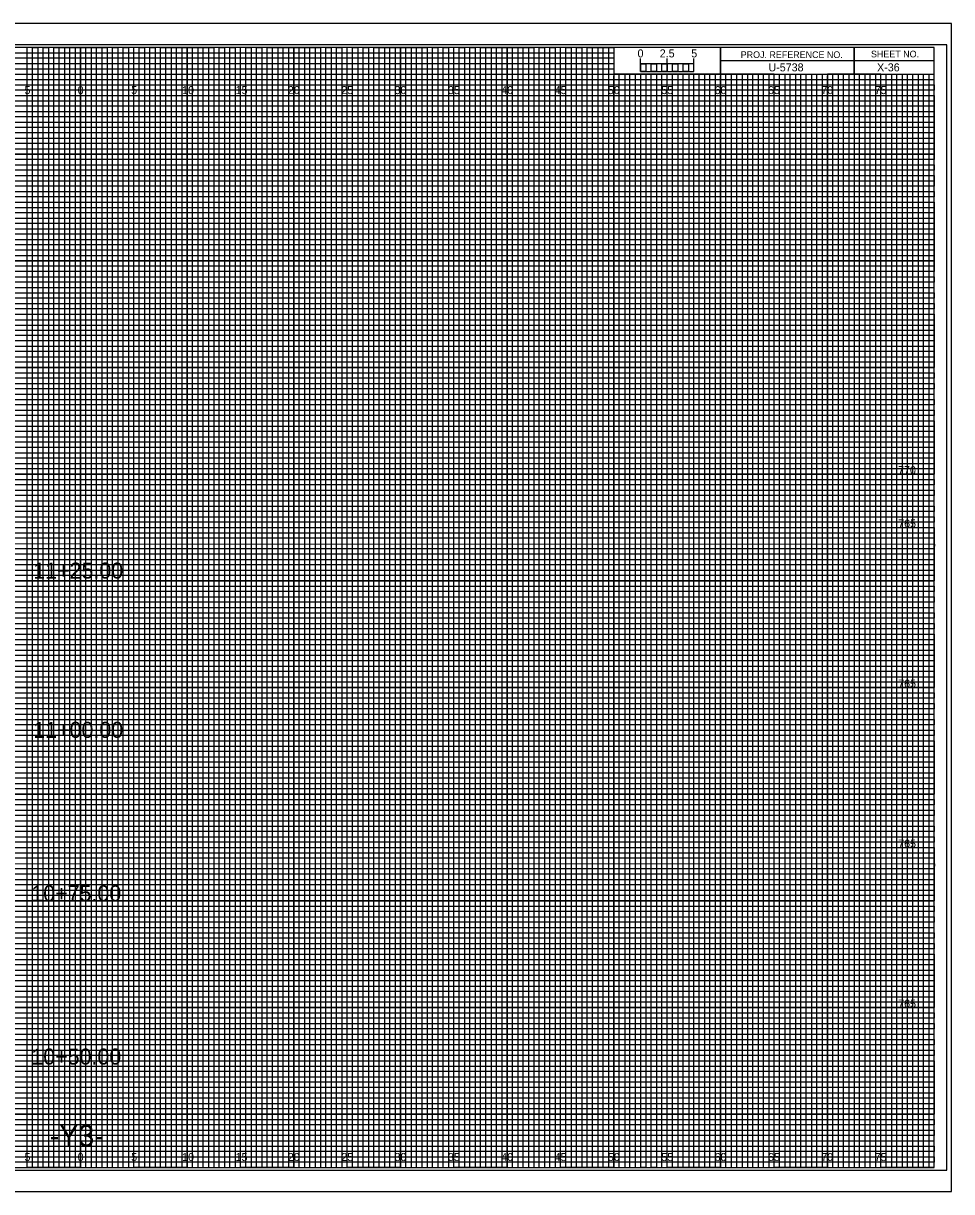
# Model space of a CAD drawing. Extents: x -7 to 162, y -2 to 107.
# Drawn here: x 74.6 to 161.7, y -2.3 to 107.3 of the extents above; entities that cross this region are included whole.
import ezdxf

# ---------------------------------------------------------------- set-up
doc = ezdxf.new("R2010")
doc.units = 0
for name, color, linetype in [('Exist XS Center Line Elevation Label', 7, 'Continuous'), ('Prop CMT Pvmt Course 1', 7, 'Continuous'), ('Prop CMT Pvmt Course 2', 7, 'Continuous'), ('Prop CMT Pvmt Course 3', 7, 'Continuous'), ('Prop CMT Pvmt Surface', 7, 'Continuous'), ('Prop CMT Pvmt Surface Shoulder', 7, 'Continuous'), ('Prop CMT Shld Paved Course 1', 7, 'Continuous'), ('Prop CMT Shld Paved Course 2', 7, 'Continuous'), ('Prop CMT Shld Paved Course 3', 7, 'Continuous'), ('Prop CMT Subgrade Earthwork', 7, 'Continuous'), ('Prop XS Alignment Label', 7, 'Continuous'), ('Prop XS Bar Scale Labels', 7, 'Continuous'), ('Prop XS Project Number', 7, 'Continuous'), ('Prop XS SE Text', 7, 'Continuous'), ('Prop XS Sheet Number', 7, 'Continuous'), ('Prop XS Station Labels', 7, 'Continuous'), ('Scratch_Level_5', 7, 'Continuous')]:
    doc.layers.add(name, color=color, linetype=linetype)

msp = doc.modelspace()

# ---------------------------------------------------------------- linework, layer by layer
at = {"layer": 'Prop CMT Pvmt Course 1'}
msp.add_lwpolyline([(-6.7, -2.25), (161.65, -2.25), (161.65, 107.25), (-6.7, 107.25)], close=True, dxfattribs=at)
at = {"layer": 'Prop CMT Pvmt Course 2'}
msp.add_lwpolyline([(-5.4, -0.25), (161.2, -0.25), (161.2, 105.25), (-5.4, 105.25)], close=True, dxfattribs=at)
at = {"layer": 'Prop CMT Pvmt Course 3'}
for p, q in [((75, 0), (75, 105)), ((80, 0), (80, 105)), ((85, 0), (85, 105)), ((90, 0), (90, 105)), ((95, 0), (95, 105)), ((100, 0), (100, 105)), ((105, 0), (105, 105)), ((110, 0), (110, 105)), ((115, 0), (115, 105)), ((120, 0), (120, 105)), ((125, 0), (125, 105)), ((130, 0), (130, 102.34)), ((135, 0), (135, 102.34)), ((140, 0), (140, 102.34)), ((145, 0), (145, 102.34)), ((150, 0), (150, 102.34)), ((155, 0), (155, 102.34)), ((0, 100), (160, 100)), ((0, 95), (160, 95)), ((0, 90), (160, 90)), ((0, 85), (160, 85)), ((0, 80), (160, 80)), ((0, 75), (160, 75)), ((0, 70), (160, 70)), ((0, 65), (160, 65)), ((0, 60), (160, 60)), ((0, 55), (160, 55)), ((0, 50), (160, 50)), ((0, 45), (160, 45)), ((0, 40), (160, 40)), ((0, 35), (160, 35)), ((0, 30), (160, 30)), ((0, 25), (160, 25)), ((0, 20), (160, 20)), ((0, 15), (160, 15)), ((0, 10), (160, 10)), ((0, 5), (160, 5))]:
    msp.add_line(p, q, dxfattribs=at)
at = {"layer": 'Prop CMT Pvmt Surface'}
for p, q in [((133.5, 102.5), (133, 102.5)), ((133, 102.5), (133, 0)), ((133.5, 0), (133.5, 102.5)), ((134.5, 102.5), (134, 102.5)), ((134, 102.5), (134, 0)), ((134.5, 0), (134.5, 102.5)), ((133, 0), (132.5, 0)), ((134, 0), (133.5, 0))]:
    msp.add_line(p, q, dxfattribs=at)
for points in [[(75, 0), (75.5, 0), (75.5, 105), (76, 105), (76, 0)], [(76, 0), (76.5, 0), (76.5, 105), (77, 105), (77, 0)], [(77.5, 0), (78, 0), (78, 105), (78.5, 105), (78.5, 0)], [(78.5, 0), (79, 0), (79, 105), (79.5, 105), (79.5, 0)], [(80, 0), (80.5, 0), (80.5, 105), (81, 105), (81, 0)], [(81, 0), (81.5, 0), (81.5, 105), (82, 105), (82, 0)], [(82.5, 0), (83, 0), (83, 105), (83.5, 105), (83.5, 0)], [(83.5, 0), (84, 0), (84, 105), (84.5, 105), (84.5, 0)], [(85, 0), (85.5, 0), (85.5, 105), (86, 105), (86, 0)], [(86, 0), (86.5, 0), (86.5, 105), (87, 105), (87, 0)], [(87.5, 0), (88, 0), (88, 105), (88.5, 105), (88.5, 0)], [(88.5, 0), (89, 0), (89, 105), (89.5, 105), (89.5, 0)], [(90, 0), (90.5, 0), (90.5, 105), (91, 105), (91, 0)], [(91, 0), (91.5, 0), (91.5, 105), (92, 105), (92, 0)], [(92.5, 0), (93, 0), (93, 105), (93.5, 105), (93.5, 0)], [(93.5, 0), (94, 0), (94, 105), (94.5, 105), (94.5, 0)], [(95, 0), (95.5, 0), (95.5, 105), (96, 105), (96, 0)], [(96, 0), (96.5, 0), (96.5, 105), (97, 105), (97, 0)], [(97.5, 0), (98, 0), (98, 105), (98.5, 105), (98.5, 0)], [(98.5, 0), (99, 0), (99, 105), (99.5, 105), (99.5, 0)], [(100, 0), (100.5, 0), (100.5, 105), (101, 105), (101, 0)], [(101, 0), (101.5, 0), (101.5, 105), (102, 105), (102, 0)], [(102.5, 0), (103, 0), (103, 105), (103.5, 105), (103.5, 0)], [(103.5, 0), (104, 0), (104, 105), (104.5, 105), (104.5, 0)], [(105, 0), (105.5, 0), (105.5, 105), (106, 105), (106, 0)], [(106, 0), (106.5, 0), (106.5, 105), (107, 105), (107, 0)], [(107.5, 0), (108, 0), (108, 105), (108.5, 105), (108.5, 0)], [(108.5, 0), (109, 0), (109, 105), (109.5, 105), (109.5, 0)], [(110, 0), (110.5, 0), (110.5, 105), (111, 105), (111, 0)], [(111, 0), (111.5, 0), (111.5, 105), (112, 105), (112, 0)], [(112.5, 0), (113, 0), (113, 105), (113.5, 105), (113.5, 0)], [(113.5, 0), (114, 0), (114, 105), (114.5, 105), (114.5, 0)], [(115, 0), (115.5, 0), (115.5, 105), (116, 105), (116, 0)], [(116, 0), (116.5, 0), (116.5, 105), (117, 105), (117, 0)], [(117.5, 0), (118, 0), (118, 105), (118.5, 105), (118.5, 0)], [(118.5, 0), (119, 0), (119, 105), (119.5, 105), (119.5, 0)], [(120, 0), (120.5, 0), (120.5, 105), (121, 105), (121, 0)], [(121, 0), (121.5, 0), (121.5, 105), (122, 105), (122, 0)], [(122.5, 0), (123, 0), (123, 105), (123.5, 105), (123.5, 0)], [(123.5, 0), (124, 0), (124, 105), (124.5, 105), (124.5, 0)], [(125, 0), (125.5, 0), (125.5, 105), (126, 105), (126, 0)], [(126, 0), (126.5, 0), (126.5, 105), (127, 105), (127, 0)], [(127.5, 0), (128, 0), (128, 105), (128.5, 105), (128.5, 0)], [(128.5, 0), (129, 0), (129, 105), (129.5, 105), (129.5, 0)], [(130, 0), (130.5, 0), (130.5, 102.5), (131.01, 102.5), (131.01, 0)], [(131, 0), (131.5, 0), (131.5, 102.5), (132, 102.5), (132, 0)], [(135, 0), (135.49, 0), (135.49, 102.5), (136, 102.5), (136, 0)], [(136, 0), (136.5, 0), (136.5, 102.5), (137.03, 102.5), (137.03, 0)], [(137.5, 0), (138, 0), (138, 102.5), (138.5, 102.5), (138.5, 0)], [(138.5, 0), (139, 0), (139, 102.5), (139.5, 102.5), (139.5, 0)], [(140, 0), (140.5, 0), (140.5, 102.5), (141, 102.5), (141, 0)], [(141, 0), (141.5, 0), (141.5, 102.5), (142, 102.5), (142, 0)], [(142.5, 0), (143, 0), (143, 102.5), (143.5, 102.5), (143.5, 0)], [(143.5, 0), (144, 0), (144, 102.5), (144.5, 102.5), (144.5, 0)], [(145, 0), (145.5, 0), (145.5, 102.5), (146, 102.5), (146, 0)], [(146, 0), (146.5, 0), (146.5, 102.5), (147, 102.5), (147, 0)], [(147.5, 0), (148, 0), (148, 102.5), (148.5, 102.5), (148.5, 0)], [(148.5, 0), (149, 0), (149, 102.5), (149.5, 102.5), (149.5, 0)], [(150, 0), (150.5, 0), (150.5, 102.5), (151, 102.5), (151, 0)], [(151, 0), (151.5, 0), (151.5, 102.5), (152, 102.5), (152, 0)], [(152.5, 0), (153, 0), (153, 102.5), (153.5, 102.5), (153.5, 0)], [(153.5, 0), (154, 0), (154, 102.5), (154.5, 102.5), (154.5, 0)], [(155, 0), (155.5, 0), (155.5, 102.5), (156, 102.5), (156, 0)], [(156, 0), (156.5, 0), (156.5, 102.5), (157, 102.5), (157, 0)], [(157.5, 0), (158, 0), (158, 102.5), (158.5, 102.5), (158.5, 0)], [(158.5, 0), (159, 0), (159, 102.5), (159.5, 102.5), (159.5, 0)]]:
    msp.add_lwpolyline(points, dxfattribs=at)
at = {"layer": 'Prop CMT Pvmt Surface Shoulder'}
for p, q in [((132.5, 102.75), (132.5, 103.95)), ((132.5, 103.45), (132.5, 103.95)), ((135, 102.75), (135, 103.95)), ((137.5, 102.75), (137.5, 103.95)), ((137.5, 103.45), (137.5, 103.95))]:
    msp.add_line(p, q, dxfattribs=at)
for points in [[(137.5, 103.45), (132.5, 103.45), (132.5, 102.75), (137.5, 102.75)], [(132.5, 103.45), (133, 103.45), (133, 102.75), (132.5, 102.75)], [(133.5, 103.45), (134, 103.45), (134, 102.75), (133.5, 102.75)], [(134.5, 103.45), (135, 103.45), (135, 102.75), (134.5, 102.75)], [(135.5, 103.45), (136, 103.45), (136, 102.75), (135.5, 102.75)], [(136.5, 103.45), (137, 103.45), (137, 102.75), (136.5, 102.75)]]:
    msp.add_lwpolyline(points, close=True, dxfattribs=at)
at = {"layer": 'Prop CMT Shld Paved Course 1'}
for p, q in [((75, 105), (70, 105)), ((75, 0), (75, 105)), ((85, 105), (80, 105)), ((80, 105), (80, 0)), ((85, 0), (85, 105)), ((95, 105), (90, 105)), ((90, 105), (90, 0)), ((95, 0), (95, 105)), ((105, 105), (100, 105)), ((100, 105), (100, 0)), ((105, 0), (105, 105)), ((115, 105), (110, 105)), ((110, 105), (110, 0)), ((115, 0), (115, 105)), ((125, 105), (120, 105)), ((120, 105), (120, 0)), ((125, 0), (125, 105)), ((130, 105), (130, 0)), ((135, 0), (135, 102.5)), ((145, 102.5), (140, 102.5)), ((140, 102.5), (140, 0)), ((145, 0), (145, 102.5)), ((155, 102.5), (150, 102.5)), ((150, 102.5), (150, 0)), ((155, 0), (155, 102.5)), ((80, 0), (75, 0)), ((90, 0), (85, 0)), ((100, 0), (95, 0)), ((110, 0), (105, 0)), ((120, 0), (115, 0)), ((130, 0), (125, 0)), ((140, 0), (135, 0)), ((150, 0), (145, 0)), ((160, 0), (155, 0)), ((160, 0), (160, 0))]:
    msp.add_line(p, q, dxfattribs=at)
for points in [[(0, 100), (160, 100), (160, 95), (0, 95)], [(0, 90), (160, 90), (160, 85), (0, 85)], [(0, 80), (160, 80), (160, 75), (0, 75)], [(0, 70), (160, 70), (160, 65), (0, 65)], [(0, 60), (160, 60), (160, 55), (0, 55)], [(0, 50), (160, 50), (160, 45), (0, 45)], [(0, 40), (160, 40), (160, 35), (0, 35)], [(0, 30), (160, 30), (160, 25), (0, 25)], [(0, 20), (160, 20), (160, 15), (0, 15)], [(0, 10), (160, 10), (160, 5), (0, 5)]]:
    msp.add_lwpolyline(points, dxfattribs=at)
at = {"layer": 'Prop CMT Shld Paved Course 2'}
for points in [[(72.5, 0), (77.5, 0), (77.5, 105), (82.5, 105), (82.5, 0), (87.5, 0), (87.5, 105), (92.5, 105), (92.5, 0), (97.5, 0), (97.5, 105), (102.5, 105), (102.5, 0), (107.5, 0), (107.5, 105), (112.5, 105), (112.5, 0), (117.5, 0), (117.5, 105), (122.5, 105), (122.5, 0), (127.5, 0), (127.5, 105), (129.97, 105), (130, 105), (130, 102.5), (132.5, 102.5), (132.5, 0), (137.5, 0), (137.5, 102.5), (142.5, 102.5), (142.5, 0), (147.5, 0), (147.5, 102.5), (152.5, 102.5), (152.5, 0), (157.5, 0), (157.5, 102.5)], [(0, 102.5), (137.5, 102.5)], [(0, 92.5), (160, 92.5), (160, 97.5), (0, 97.5)], [(0, 82.5), (160, 82.5), (160, 87.5), (0, 87.5)], [(0, 72.5), (160, 72.5), (160, 77.5), (0, 77.5)], [(0, 62.5), (160, 62.5), (160, 67.5), (0, 67.5)], [(0, 52.5), (160, 52.5), (160, 57.5), (0, 57.5)], [(0, 42.5), (160, 42.5), (160, 47.5), (0, 47.5)], [(0, 32.5), (160, 32.5), (160, 37.5), (0, 37.5)], [(0, 22.5), (160, 22.5), (160, 27.5), (0, 27.5)], [(0, 12.5), (160, 12.5), (160, 17.5), (0, 17.5)], [(0, 2.5), (160, 2.5), (160, 7.5), (0, 7.5)]]:
    msp.add_lwpolyline(points, dxfattribs=at)
at = {"layer": 'Prop CMT Shld Paved Course 3'}
for p, q in [((0, 104.5), (130, 104.5)), ((130, 104.5), (130, 103.99)), ((130, 103.99), (0, 103.99)), ((0, 103.5), (130, 103.5)), ((130, 102.95), (0, 102.95)), ((130, 103.5), (130, 102.95)), ((0, 102), (160, 102))]:
    msp.add_line(p, q, dxfattribs=at)
for points in [[(0, 101.5), (135, 101.5), (160, 101.5), (160, 101), (0, 101)], [(0, 100.5), (160, 100.5), (160, 99.5), (0, 99.5)], [(0, 99), (160, 99), (160, 98.5), (0, 98.49)], [(0, 98), (160, 98), (160, 97), (0, 97)], [(0, 96.5), (160, 96.5), (160, 96), (0, 96)], [(0, 95.5), (160, 95.5), (160, 94.5), (0, 94.5)], [(0, 94), (160, 94), (160, 93.5), (0, 93.5)], [(0, 93), (160, 93), (160, 92), (0, 92)], [(0, 91.5), (160, 91.5), (160, 91), (0, 91)], [(0, 90.5), (160, 90.5), (160, 89.5), (0, 89.5)], [(0, 89), (160, 89), (160, 88.5), (0, 88.5)], [(0, 88), (160, 88), (160, 86.98), (160, 86.5), (160, 86), (0, 86)], [(0, 87), (160, 87), (160, 86.5), (0, 86.5)], [(0, 85.5), (160, 85.5), (160, 84.5), (0, 84.52)], [(0, 84.52), (160, 84.5), (160, 84), (0, 84)], [(0, 83.5), (160, 83.5), (160, 83), (0, 83)], [(0, 82), (160, 82), (160, 81.5), (0, 81.5)], [(0, 81), (160, 81), (160, 80.5), (0, 80.5)], [(-0.04, 79.45), (160, 79.45), (160, 78.94), (-0.04, 78.94)], [(0, 78.5), (160, 78.5), (160, 78), (0, 78)], [(0, 77), (160, 77), (160, 76.5), (0, 76.5)], [(0, 76), (160, 76), (160, 75.5), (0, 75.5)], [(0, 74.5), (160, 74.5), (160, 74), (0, 74)], [(0, 73.5), (160, 73.5), (160, 73), (0, 73)], [(0, 72), (160, 72), (160, 71.5), (0, 71.5)], [(0, 71), (160, 71), (160, 70.5), (0, 70.5)], [(0, 69.5), (160, 69.5), (160, 68.99), (0, 69)], [(0, 68.5), (160, 68.5), (160, 68), (0, 68)], [(0, 67), (160, 67), (160, 66.5), (0, 66.5)], [(0, 66), (160, 66), (160, 65.5), (0, 65.5)], [(0, 64.5), (160, 64.5), (160, 64), (0, 64)], [(0, 63.5), (160, 63.5), (160, 63), (0, 63)], [(0, 62), (160, 62), (160, 61.5), (0, 61.5)], [(0, 61), (160, 61), (160, 60.5), (0, 60.5)], [(0, 59.5), (160, 59.5), (160, 59), (0, 59)], [(0, 58.5), (160.03, 58.45), (160, 58), (0, 58)], [(0, 57), (160, 57), (160, 56.5), (0, 56.5)], [(0, 56), (160, 56), (160, 55.5), (0, 55.5)], [(0, 54.5), (160, 54.5), (160, 54), (0, 54)], [(0, 53.5), (160, 53.5), (160, 53), (0, 53)], [(0, 52), (160, 52), (160, 51.5), (0, 51.5)], [(0, 51), (160, 51), (160, 50.5), (0, 50.5)], [(0, 49.5), (160, 49.5), (160, 49), (0, 49)], [(0, 48.5), (160, 48.5), (160, 48), (0, 48)], [(0, 47), (160, 47), (160, 46.5), (0, 46.5)], [(0, 46), (160, 46), (160, 45.5), (0, 45.5)], [(0, 44.5), (160, 44.5), (160, 44), (0, 44)], [(0, 43.5), (160, 43.5), (160, 43), (0, 43)], [(0, 42), (160, 42), (160, 41.5), (0, 41.5)], [(0, 41), (160, 41), (160, 40.5), (0, 40.5)], [(0, 39.5), (160, 39.5), (160, 38.99), (0, 39)], [(0, 38.5), (160, 38.5), (160, 38), (0, 38)], [(0, 37), (160, 37), (160, 36.5), (0, 36.5)], [(0, 36), (160, 36), (160, 35.5), (0, 35.5)], [(0, 34.5), (160, 34.5), (160, 34), (0, 34)], [(0, 33.5), (160, 33.5), (160, 33), (0, 33)], [(0, 32), (160, 32), (160, 31.5), (0, 31.5)], [(0, 31), (160, 31), (160, 30.5), (0, 30.5)], [(0, 29.5), (160, 29.5), (160, 29), (0, 29)], [(0, 28.5), (160.03, 28.46), (160, 28), (0, 28)], [(0, 27), (160, 27), (160, 26.5), (0, 26.5)], [(0, 26), (160, 26), (160, 25.5), (0, 25.5)], [(0, 24.5), (160, 24.5), (160, 24), (0, 24)], [(0, 23.5), (160, 23.5), (160, 23), (0, 23)], [(0, 22), (160, 22), (160, 21.5), (0, 21.5)], [(0, 21), (160, 21), (160, 20.5), (0, 20.5)], [(0, 19.5), (160, 19.5), (160, 19), (0, 19)], [(0, 18.5), (160, 18.5), (160, 18), (0, 18)], [(0, 17), (160, 17), (160, 16.5), (0, 16.5)], [(0, 16), (160, 16), (160, 15.5), (0, 15.5)], [(0, 14.5), (160, 14.5), (160, 14), (0, 14)], [(0, 13.5), (160, 13.5), (160, 13), (0, 13)], [(0, 12), (160, 12), (160, 11.5), (0, 11.5)], [(0, 11), (160, 11), (160, 10.5), (0, 10.5)], [(0, 9.5), (160, 9.5), (160, 9), (0, 9)], [(0, 8.5), (160, 8.5), (160, 8), (0, 8)], [(0, 7), (160, 7), (160, 6.5), (0, 6.5)], [(0, 6), (160, 6), (160, 5.5), (0, 5.5)], [(0, 4.5), (160, 4.5), (160, 4), (0, 4)], [(0, 3.5), (160, 3.5), (160, 3), (0, 3)], [(0, 2), (160, 2), (160, 1.5), (0, 1.5)], [(0, 1), (160, 1), (160, 0.5), (0, 0.5)]]:
    msp.add_lwpolyline(points, dxfattribs=at)
at = {"layer": 'Prop CMT Subgrade Earthwork'}
for p, q in [((152.5, 105), (152.5, 102.5)), ((152.5, 102.5), (152.5, 105)), ((160, 103.75), (140, 103.75)), ((140, 103.75), (140, 102.5)), ((140, 102.5), (160, 102.5))]:
    msp.add_line(p, q, dxfattribs=at)
for points in [[(160, 105), (0, 105), (0, 0), (160, 0)], [(140, 105), (130, 105), (130, 102.52), (140, 102.52)], [(160, 105), (140, 105), (140, 102.5), (160, 102.5)]]:
    msp.add_lwpolyline(points, close=True, dxfattribs=at)
at = {"layer": 'Prop XS SE Text'}
for p, q in [((161.65, 107.25), (-6.7, 107.25)), ((-6.7, -2.25), (161.65, -2.25))]:
    msp.add_line(p, q, dxfattribs=at)

# ---------------------------------------------------------------- texts
at = {"layer": 'Exist XS Center Line Elevation Label'}
for s, p in [('5', (74.74, 100.62)), ('0', (79.73, 100.62)), ('0', (79.73, 100.62)), ('5', (84.74, 100.62)), ('10', (89.52, 100.62)), ('15', (94.53, 100.62)), ('20', (99.43, 100.62)), ('25', (104.44, 100.62)), ('30', (109.43, 100.62)), ('35', (114.44, 100.62)), ('40', (119.43, 100.62)), ('45', (124.44, 100.62)), ('50', (129.43, 100.62)), ('55', (134.44, 100.62)), ('60', (139.43, 100.62)), ('65', (144.44, 100.62)), ('70', (149.43, 100.62)), ('75', (154.44, 100.62)), ('5', (74.74, 0.62)), ('0', (79.73, 0.62)), ('0', (79.73, 0.62)), ('5', (84.74, 0.62)), ('10', (89.52, 0.62)), ('15', (94.53, 0.62)), ('20', (99.43, 0.62)), ('25', (104.44, 0.62)), ('30', (109.43, 0.62)), ('35', (114.44, 0.62)), ('40', (119.43, 0.62)), ('45', (124.44, 0.62)), ('50', (129.43, 0.62)), ('55', (134.44, 0.62)), ('60', (139.43, 0.62)), ('65', (144.44, 0.62)), ('70', (149.43, 0.62)), ('75', (154.44, 0.62))]:
    msp.add_text(s, height=0.75, dxfattribs=at).set_placement(p)
at = {"layer": 'Prop CMT Pvmt Surface Shoulder'}
msp.add_text('0', height=0.75, dxfattribs=at).set_placement((132.21, 104.06))
at = {"layer": 'Prop CMT Subgrade Earthwork'}
for s, p in [('PROJ. REFERENCE NO.', (141.88, 104)), ('SHEET NO.', (154.09, 104.06))]:
    msp.add_text(s, height=0.625, dxfattribs=at).set_placement(p)
at = {"layer": 'Prop XS Alignment Label'}
msp.add_text('-Y3-', height=2, dxfattribs=at).set_placement((77.12, 2))
at = {"layer": 'Prop XS Bar Scale Labels'}
for s, p in [('2.5', (134.29, 104.06)), ('5', (137.24, 104.06))]:
    msp.add_text(s, height=0.75, dxfattribs=at).set_placement(p)
at = {"layer": 'Prop XS Project Number'}
msp.add_text('U-5738', height=0.75, dxfattribs=at).set_placement((144.48, 102.75))
at = {"layer": 'Prop XS Sheet Number'}
msp.add_text('X-36', height=0.75, dxfattribs=at).set_placement((154.66, 102.75))
at = {"layer": 'Prop XS Station Labels'}
for s, p in [('11+25.00', (75.57, 55.21)), ('11+00.00', (75.57, 40.28)), ('10+75.00', (75.39, 24.96)), ('10+50.00', (75.39, 9.66))]:
    msp.add_text(s, height=1.5, dxfattribs=at).set_placement(p)
at = {"layer": 'Scratch_Level_5'}
for s, p in [('770', (156.63, 65)), ('765', (156.64, 60)), ('765', (156.64, 45)), ('765', (156.64, 30)), ('765', (156.64, 15))]:
    msp.add_text(s, height=0.75, dxfattribs=at).set_placement(p)

doc.saveas('drawing.dxf')
